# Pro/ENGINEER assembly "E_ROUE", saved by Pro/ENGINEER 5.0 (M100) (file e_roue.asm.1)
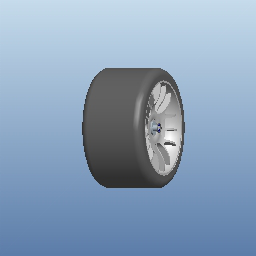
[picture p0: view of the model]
Units: millimeter Newton Second (mmNs); MM, TONNE, HOURS

Other components: NOIX_CARDAN-ROUE_A0, 80655614-CARRE_ROUE_14_A0, ROUE_A0, RONDELLE_PLATE-D6, ECROU_HFR_M6_

Other named items: NOIX_CARDAN-ROUE_01, 80655614-CARRE_ROUE_14_01, A-DROITE, A-DESSUS, A-FACE, A-R0, ACS0, ACS1, ACS2, ACS3, ACS4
